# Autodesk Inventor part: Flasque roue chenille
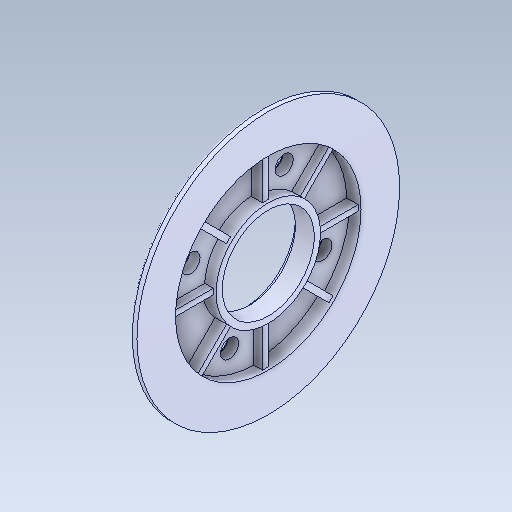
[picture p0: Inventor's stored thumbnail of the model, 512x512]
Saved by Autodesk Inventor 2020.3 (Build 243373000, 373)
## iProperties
Created: 2018-09
Part Number: Flasque roue chenille
Material: Générique
Document SubType Name: Modeling
Designer: ficho
Density: 1 g/cm^3
Appearance: Par défaut
Mass: 2.81922 g
Surface Area: 40.9931 cm^2
Volume: 2.81922 cm^3
Sending System: SolidWorks 2015
Last Author: adrien
Last Saved: 2018-09-12
Author: ficho
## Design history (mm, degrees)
feature "Chanfrein1"
node "Solide1"
